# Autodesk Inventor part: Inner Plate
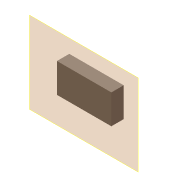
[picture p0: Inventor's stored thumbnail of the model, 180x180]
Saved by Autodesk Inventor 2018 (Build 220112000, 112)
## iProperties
Created: 2017-06
Part Number: Inner Plate
Material: Generic
Document SubType Name: Modeling
Designer: CADCIM 00
Density: 1 g/cm^3
Appearance: Default
Author: CADCIM 00
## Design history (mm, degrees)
workplane "Work Plane1"
sketch "Sketch1"
  geometry: L1 (-20, 10)-(20, 10); L2 (20, 10)-(20, -10); L3 (20, -10)-(-20, -10); L4 (-20, -10)-(-20, 10); 1 further point
  constraints: 8 end point, 2 parallel, 1 horizontal, 1 perpendicular
workplane "Work Plane2"
extrude "Extrusion1" new body sketch "Sketch1" stored distance "d0" = 25.4; taper "d1" = 0 deg
body "Solid1"
